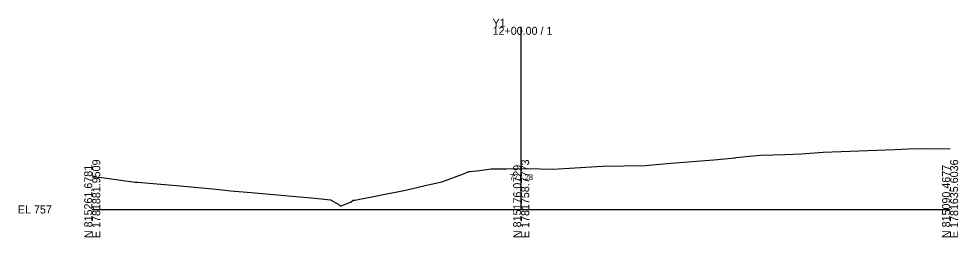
# Model space of a CAD drawing. Extents: x -26 to 3603, y -10 to 9847.
# Drawn here: x -25.7 to 302.8, y 1990.3 to 2066.7 of the extents above; entities that cross this region are included whole.
import ezdxf

# ---------------------------------------------------------------- set-up
doc = ezdxf.new("R2010")
doc.units = 0
for name, color, linetype in [('Exist Cross Section Cell', 7, 'Continuous'), ('Exist XS Center Line Elevation Label', 7, 'Continuous'), ('Exist XS Ground Line', 7, 'Continuous')]:
    doc.layers.add(name, color=color, linetype=linetype)

msp = doc.modelspace()

# ---------------------------------------------------------------- linework, layer by layer
at = {"layer": 'Exist Cross Section Cell'}
for p, q in [((150, 2000), (150, 2063.87)), ((0, 2000), (150, 2000)), ((150, 2000), (300, 2000))]:
    msp.add_line(p, q, dxfattribs=at)
at = {"layer": 'Exist XS Ground Line'}
for p, q in [((255.67, 2019.99), (280.72, 2020.95)), ((280.72, 2020.95), (285.32, 2021.23)), ((285.32, 2021.23), (290.82, 2021.29)), ((290.82, 2021.29), (300, 2021.18)), ((202.36, 2016.2), (217.42, 2017.4)), ((217.42, 2017.4), (224.83, 2018.09)), ((224.83, 2018.09), (225.19, 2018.13)), ((225.19, 2018.13), (229.71, 2018.7)), ((229.71, 2018.7), (233.66, 2018.95)), ((233.66, 2018.95), (242.37, 2019.26)), ((242.37, 2019.26), (247.99, 2019.49)), ((247.99, 2019.49), (255.67, 2019.99)), ((135.45, 2013.64), (139.51, 2014.18)), ((139.51, 2014.18), (144.78, 2014.23)), ((144.78, 2014.23), (150.24, 2014.28)), ((150.24, 2014.28), (156.65, 2014.19)), ((156.65, 2014.19), (161.12, 2014.15)), ((161.12, 2014.15), (178.47, 2015.16)), ((178.47, 2015.16), (193.4, 2015.34)), ((193.4, 2015.34), (202.36, 2016.2)), ((0, 2011.37), (3.33, 2011.13)), ((3.33, 2011.13), (15.04, 2009.6)), ((122.29, 2009.71), (129.87, 2012.52)), ((129.87, 2012.52), (131.71, 2013.27)), ((131.71, 2013.27), (132.22, 2013.33)), ((132.22, 2013.33), (135.45, 2013.64)), ((15.04, 2009.6), (15.82, 2009.5)), ((15.82, 2009.5), (29.48, 2008.37)), ((29.48, 2008.37), (35.79, 2007.77)), ((35.79, 2007.77), (43.35, 2007.05)), ((109.5, 2006.73), (116.38, 2008.35)), ((116.38, 2008.35), (122.29, 2009.71)), ((43.35, 2007.05), (48.47, 2006.55)), ((48.47, 2006.55), (55.54, 2005.89)), ((55.54, 2005.89), (77.87, 2003.91)), ((91.84, 2003.31), (109.5, 2006.73)), ((77.87, 2003.91), (83.31, 2003.4)), ((83.31, 2003.4), (86.25, 2001.76)), ((86.25, 2001.76), (86.86, 2001.17)), ((86.86, 2001.17), (90.55, 2002.67)), ((90.55, 2002.67), (91.26, 2003.25)), ((91.26, 2003.25), (91.84, 2003.31))]:
    msp.add_line(p, q, dxfattribs=at)

# ---------------------------------------------------------------- texts
at = {"layer": 'Exist Cross Section Cell'}
for s, p in [('Y1', (140, 2063.87)), ('12+00.00 / 1', (140, 2061.07)), ('EL 757', (-26, 1998.6))]:
    msp.add_text(s, height=2.8, dxfattribs=at).set_placement(p)
for s, p in [('E 1781881.9509', (2.8, 1990)), ('E 1781758.7773', (152.8, 1990)), ('E 1781635.6036', (302.8, 1990)), ('N 815261.6781', (0, 1990)), ('N 815176.0729', (150, 1990)), ('N 815090.4677', (300, 1990))]:
    msp.add_text(s, height=2.8, rotation=90, dxfattribs=at).set_placement(p)
at = {"layer": 'Exist XS Center Line Elevation Label'}
msp.add_text('771.28', height=2, dxfattribs=at).set_placement((145.96, 2010.28))

doc.saveas('drawing.dxf')
